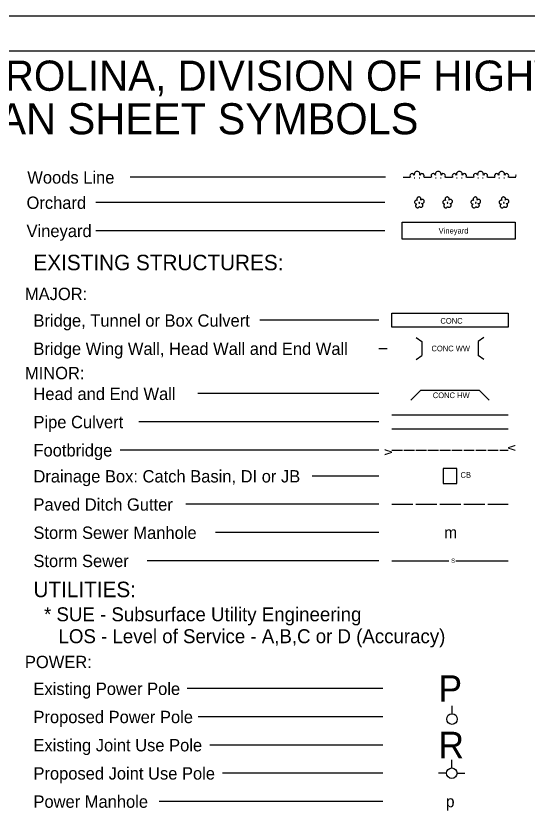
# Model space of a CAD drawing. Extents: x 573077.9 to 573111.9, y -55204.3 to -55182.3.
# Drawn here: x 573096.48 to 573103.74, y -55193.68 to -55182.3 of the extents above; entities that cross this region are included whole.
import ezdxf

# ---------------------------------------------------------------- set-up
doc = ezdxf.new("R2010")
doc.units = 0
doc.layers.add('Sheet Plot Border Inside CELL', color=7, linetype='Continuous')
doc.layers.add('Sheet Symbology CELL', color=7, linetype='Continuous')

msp = doc.modelspace()

# ---------------------------------------------------------------- linework, layer by layer
at = {"layer": 'Sheet Plot Border Inside CELL'}
msp.add_lwpolyline([(573077.854, -55204.298), (573111.854, -55204.298), (573111.854, -55182.298), (573077.854, -55182.298)], close=True, dxfattribs=at)
at = {"layer": 'Sheet Symbology CELL'}
for p, q in [((573101.719, -55184.584), (573098.097, -55184.584)), ((573101.967, -55184.584), (573102.067, -55184.584)), ((573102.126, -55184.594), (573102.136, -55184.594)), ((573102.196, -55184.594), (573102.206, -55184.594)), ((573102.267, -55184.584), (573102.367, -55184.584)), ((573102.426, -55184.594), (573102.436, -55184.594)), ((573102.496, -55184.594), (573102.506, -55184.594)), ((573102.567, -55184.584), (573102.667, -55184.584)), ((573102.726, -55184.594), (573102.736, -55184.594)), ((573102.796, -55184.594), (573102.806, -55184.594)), ((573102.867, -55184.584), (573102.967, -55184.584)), ((573103.026, -55184.594), (573103.036, -55184.594)), ((573103.096, -55184.594), (573103.106, -55184.594)), ((573103.167, -55184.584), (573103.267, -55184.584)), ((573103.326, -55184.594), (573103.336, -55184.594)), ((573103.396, -55184.594), (573103.406, -55184.594)), ((573103.467, -55184.584), (573103.567, -55184.584)), ((573101.708, -55184.942), (573097.609, -55184.942)), ((573101.708, -55185.342), (573097.609, -55185.342)), ((573101.622, -55186.612), (573099.933, -55186.612)), ((573102.151, -55186.855), (573102.233, -55186.912)), ((573103.115, -55186.855), (573103.033, -55186.912)), ((573102.233, -55186.912), (573102.233, -55187.112)), ((573103.033, -55186.912), (573103.033, -55187.112)), ((573101.622, -55187.012), (573101.742, -55187.012)), ((573102.151, -55187.17), (573102.233, -55187.112)), ((573103.115, -55187.17), (573103.033, -55187.112)), ((573101.622, -55187.652), (573099.056, -55187.652)), ((573102.079, -55187.744), (573102.22, -55187.602)), ((573102.22, -55187.602), (573103.045, -55187.602)), ((573103.045, -55187.602), (573103.187, -55187.744)), ((573101.808, -55187.952), (573103.458, -55187.952)), ((573101.622, -55188.052), (573098.218, -55188.052)), ((573101.808, -55188.152), (573103.458, -55188.152)), ((573101.622, -55188.452), (573097.952, -55188.452)), ((573101.808, -55188.452), (573101.958, -55188.452)), ((573101.978, -55188.452), (573102.128, -55188.452)), ((573102.148, -55188.452), (573102.298, -55188.452)), ((573102.318, -55188.452), (573102.468, -55188.452)), ((573102.488, -55188.452), (573102.638, -55188.452)), ((573102.658, -55188.452), (573102.808, -55188.452)), ((573102.828, -55188.452), (573102.978, -55188.452)), ((573102.998, -55188.452), (573103.148, -55188.452)), ((573103.168, -55188.452), (573103.318, -55188.452)), ((573103.338, -55188.452), (573103.458, -55188.452)), ((573101.622, -55188.821), (573100.678, -55188.821)), ((573101.622, -55189.221), (573098.883, -55189.221)), ((573101.808, -55189.221), (573102.108, -55189.221)), ((573102.148, -55189.221), (573102.448, -55189.221)), ((573102.488, -55189.221), (573102.788, -55189.221)), ((573102.828, -55189.221), (573103.128, -55189.221)), ((573103.168, -55189.221), (573103.458, -55189.221)), ((573101.622, -55189.621), (573099.308, -55189.621)), ((573101.622, -55190.021), (573098.338, -55190.021)), ((573101.808, -55190.021), (573102.618, -55190.021)), ((573102.718, -55190.021), (573103.458, -55190.021)), ((573101.678, -55191.835), (573098.904, -55191.835)), ((573102.662, -55192.192), (573102.662, -55192.08)), ((573101.678, -55192.235), (573099.059, -55192.235)), ((573101.678, -55192.635), (573099.227, -55192.635)), ((573102.658, -55192.959), (573102.658, -55192.847)), ((573101.678, -55193.035), (573099.407, -55193.035)), ((573102.583, -55193.034), (573102.47, -55193.034)), ((573102.733, -55193.034), (573102.845, -55193.034)), ((573101.678, -55193.435), (573098.508, -55193.435))]:
    msp.add_line(p, q, dxfattribs=at)
for points in [[(573111.354, -55182.798), (573081.354, -55182.798), (573081.354, -55203.778), (573111.354, -55203.778)], [(573102.537, -55188.927), (573102.729, -55188.927), (573102.729, -55188.715), (573102.537, -55188.715)]]:
    msp.add_lwpolyline(points, close=True, dxfattribs=at)
for points in [[(573102.217, -55184.907), (573102.22, -55184.901), (573102.221, -55184.895), (573102.22, -55184.889), (573102.219, -55184.883), (573102.216, -55184.878), (573102.213, -55184.873), (573102.208, -55184.869), (573102.203, -55184.866), (573102.196, -55184.864), (573102.191, -55184.864), (573102.185, -55184.865), (573102.179, -55184.867), (573102.174, -55184.87), (573102.169, -55184.874), (573102.166, -55184.88), (573102.164, -55184.885), (573102.163, -55184.891), (573102.163, -55184.897), (573102.164, -55184.903), (573102.167, -55184.908), (573102.171, -55184.914), (573102.166, -55184.911), (573102.16, -55184.91), (573102.154, -55184.91), (573102.149, -55184.912), (573102.144, -55184.914), (573102.139, -55184.918), (573102.135, -55184.922), (573102.132, -55184.927), (573102.131, -55184.932), (573102.13, -55184.939), (573102.131, -55184.944), (573102.133, -55184.949), (573102.137, -55184.954), (573102.14, -55184.958), (573102.145, -55184.961), (573102.151, -55184.964), (573102.156, -55184.965), (573102.162, -55184.965), (573102.157, -55184.967), (573102.152, -55184.971), (573102.149, -55184.975), (573102.147, -55184.981), (573102.145, -55184.987), (573102.145, -55184.992), (573102.146, -55184.998), (573102.149, -55185.003), (573102.152, -55185.008), (573102.156, -55185.012), (573102.161, -55185.015), (573102.166, -55185.017), (573102.172, -55185.017), (573102.178, -55185.017), (573102.183, -55185.016), (573102.188, -55185.012), (573102.193, -55185.009), (573102.198, -55185)], [(573102.2, -55184.942), (573102.197, -55184.942), (573102.195, -55184.943), (573102.193, -55184.944), (573102.193, -55184.947), (573102.193, -55184.949), (573102.195, -55184.951), (573102.198, -55184.951), (573102.2, -55184.951), (573102.202, -55184.949), (573102.203, -55184.946), (573102.202, -55184.944), (573102.2, -55184.942)], [(573102.198, -55185), (573102.21, -55185.007), (573102.216, -55185.009), (573102.222, -55185.01), (573102.228, -55185.009), (573102.233, -55185.007), (573102.238, -55185.004), (573102.243, -55185), (573102.246, -55184.995), (573102.248, -55184.99), (573102.25, -55184.984), (573102.249, -55184.978), (573102.248, -55184.972), (573102.244, -55184.966), (573102.241, -55184.962), (573102.236, -55184.959), (573102.23, -55184.956), (573102.236, -55184.957), (573102.243, -55184.957), (573102.248, -55184.955), (573102.254, -55184.952), (573102.259, -55184.949), (573102.263, -55184.944), (573102.266, -55184.938), (573102.267, -55184.932), (573102.268, -55184.926), (573102.267, -55184.92), (573102.265, -55184.914), (573102.261, -55184.909), (573102.256, -55184.904), (573102.251, -55184.901), (573102.245, -55184.899), (573102.239, -55184.898), (573102.233, -55184.898), (573102.227, -55184.9), (573102.222, -55184.903), (573102.217, -55184.907)], [(573102.617, -55184.907), (573102.62, -55184.901), (573102.621, -55184.895), (573102.62, -55184.889), (573102.619, -55184.883), (573102.616, -55184.878), (573102.613, -55184.873), (573102.608, -55184.869), (573102.603, -55184.866), (573102.596, -55184.864), (573102.591, -55184.864), (573102.585, -55184.865), (573102.579, -55184.867), (573102.574, -55184.87), (573102.569, -55184.874), (573102.566, -55184.88), (573102.564, -55184.885), (573102.563, -55184.891), (573102.563, -55184.897), (573102.564, -55184.903), (573102.567, -55184.908), (573102.571, -55184.914), (573102.566, -55184.911), (573102.56, -55184.91), (573102.554, -55184.91), (573102.549, -55184.912), (573102.544, -55184.914), (573102.539, -55184.918), (573102.535, -55184.922), (573102.532, -55184.927), (573102.531, -55184.932), (573102.53, -55184.939), (573102.531, -55184.944), (573102.533, -55184.949), (573102.537, -55184.954), (573102.54, -55184.958), (573102.545, -55184.961), (573102.551, -55184.964), (573102.556, -55184.965), (573102.562, -55184.965), (573102.557, -55184.967), (573102.552, -55184.971), (573102.549, -55184.975), (573102.547, -55184.981), (573102.545, -55184.987), (573102.545, -55184.992), (573102.546, -55184.998), (573102.549, -55185.003), (573102.552, -55185.008), (573102.556, -55185.012), (573102.561, -55185.015), (573102.566, -55185.017), (573102.572, -55185.017), (573102.578, -55185.017), (573102.583, -55185.016), (573102.588, -55185.012), (573102.593, -55185.009), (573102.598, -55185)], [(573102.6, -55184.942), (573102.597, -55184.942), (573102.595, -55184.943), (573102.593, -55184.944), (573102.593, -55184.947), (573102.593, -55184.949), (573102.595, -55184.951), (573102.598, -55184.951), (573102.6, -55184.951), (573102.602, -55184.949), (573102.603, -55184.946), (573102.602, -55184.944), (573102.6, -55184.942)], [(573102.598, -55185), (573102.61, -55185.007), (573102.616, -55185.009), (573102.622, -55185.01), (573102.628, -55185.009), (573102.633, -55185.007), (573102.638, -55185.004), (573102.643, -55185), (573102.646, -55184.995), (573102.648, -55184.99), (573102.65, -55184.984), (573102.649, -55184.978), (573102.648, -55184.972), (573102.644, -55184.966), (573102.641, -55184.962), (573102.636, -55184.959), (573102.63, -55184.956), (573102.636, -55184.957), (573102.643, -55184.957), (573102.648, -55184.955), (573102.654, -55184.952), (573102.659, -55184.949), (573102.663, -55184.944), (573102.666, -55184.938), (573102.667, -55184.932), (573102.668, -55184.926), (573102.667, -55184.92), (573102.665, -55184.914), (573102.661, -55184.909), (573102.656, -55184.904), (573102.651, -55184.901), (573102.645, -55184.899), (573102.639, -55184.898), (573102.633, -55184.898), (573102.627, -55184.9), (573102.622, -55184.903), (573102.617, -55184.907)], [(573103.017, -55184.907), (573103.02, -55184.901), (573103.021, -55184.895), (573103.02, -55184.889), (573103.019, -55184.883), (573103.016, -55184.878), (573103.013, -55184.873), (573103.008, -55184.869), (573103.003, -55184.866), (573102.996, -55184.864), (573102.991, -55184.864), (573102.985, -55184.865), (573102.979, -55184.867), (573102.974, -55184.87), (573102.969, -55184.874), (573102.966, -55184.88), (573102.964, -55184.885), (573102.963, -55184.891), (573102.963, -55184.897), (573102.964, -55184.903), (573102.967, -55184.908), (573102.971, -55184.914), (573102.966, -55184.911), (573102.96, -55184.91), (573102.954, -55184.91), (573102.949, -55184.912), (573102.944, -55184.914), (573102.939, -55184.918), (573102.935, -55184.922), (573102.932, -55184.927), (573102.931, -55184.932), (573102.93, -55184.939), (573102.931, -55184.944), (573102.933, -55184.949), (573102.937, -55184.954), (573102.94, -55184.958), (573102.945, -55184.961), (573102.951, -55184.964), (573102.956, -55184.965), (573102.962, -55184.965), (573102.957, -55184.967), (573102.952, -55184.971), (573102.949, -55184.975), (573102.947, -55184.981), (573102.945, -55184.987), (573102.945, -55184.992), (573102.946, -55184.998), (573102.949, -55185.003), (573102.952, -55185.008), (573102.956, -55185.012), (573102.961, -55185.015), (573102.966, -55185.017), (573102.972, -55185.017), (573102.978, -55185.017), (573102.983, -55185.016), (573102.988, -55185.012), (573102.993, -55185.009), (573102.998, -55185)], [(573103, -55184.942), (573102.997, -55184.942), (573102.995, -55184.943), (573102.993, -55184.944), (573102.993, -55184.947), (573102.993, -55184.949), (573102.995, -55184.951), (573102.998, -55184.951), (573103, -55184.951), (573103.002, -55184.949), (573103.003, -55184.946), (573103.002, -55184.944), (573103, -55184.942)], [(573102.998, -55185), (573103.01, -55185.007), (573103.016, -55185.009), (573103.022, -55185.01), (573103.028, -55185.009), (573103.033, -55185.007), (573103.038, -55185.004), (573103.043, -55185), (573103.046, -55184.995), (573103.048, -55184.99), (573103.05, -55184.984), (573103.049, -55184.978), (573103.048, -55184.972), (573103.044, -55184.966), (573103.041, -55184.962), (573103.036, -55184.959), (573103.03, -55184.956), (573103.036, -55184.957), (573103.043, -55184.957), (573103.048, -55184.955), (573103.054, -55184.952), (573103.059, -55184.949), (573103.063, -55184.944), (573103.066, -55184.938), (573103.067, -55184.932), (573103.068, -55184.926), (573103.067, -55184.92), (573103.065, -55184.914), (573103.061, -55184.909), (573103.056, -55184.904), (573103.051, -55184.901), (573103.045, -55184.899), (573103.039, -55184.898), (573103.033, -55184.898), (573103.027, -55184.9), (573103.022, -55184.903), (573103.017, -55184.907)], [(573103.417, -55184.907), (573103.42, -55184.901), (573103.421, -55184.895), (573103.42, -55184.889), (573103.419, -55184.883), (573103.416, -55184.878), (573103.413, -55184.873), (573103.408, -55184.869), (573103.403, -55184.866), (573103.396, -55184.864), (573103.391, -55184.864), (573103.385, -55184.865), (573103.379, -55184.867), (573103.374, -55184.87), (573103.369, -55184.874), (573103.366, -55184.88), (573103.364, -55184.885), (573103.363, -55184.891), (573103.363, -55184.897), (573103.364, -55184.903), (573103.367, -55184.908), (573103.371, -55184.914), (573103.366, -55184.911), (573103.36, -55184.91), (573103.354, -55184.91), (573103.349, -55184.912), (573103.344, -55184.914), (573103.339, -55184.918), (573103.335, -55184.922), (573103.332, -55184.927), (573103.331, -55184.932), (573103.33, -55184.939), (573103.331, -55184.944), (573103.333, -55184.949), (573103.337, -55184.954), (573103.34, -55184.958), (573103.345, -55184.961), (573103.351, -55184.964), (573103.356, -55184.965), (573103.362, -55184.965), (573103.357, -55184.967), (573103.352, -55184.971), (573103.349, -55184.975), (573103.347, -55184.981), (573103.345, -55184.987), (573103.345, -55184.992), (573103.346, -55184.998), (573103.349, -55185.003), (573103.352, -55185.008), (573103.356, -55185.012), (573103.361, -55185.015), (573103.366, -55185.017), (573103.372, -55185.017), (573103.378, -55185.017), (573103.383, -55185.016), (573103.388, -55185.012), (573103.393, -55185.009), (573103.398, -55185)], [(573103.4, -55184.942), (573103.397, -55184.942), (573103.395, -55184.943), (573103.393, -55184.944), (573103.393, -55184.947), (573103.393, -55184.949), (573103.395, -55184.951), (573103.398, -55184.951), (573103.4, -55184.951), (573103.402, -55184.949), (573103.403, -55184.946), (573103.402, -55184.944), (573103.4, -55184.942)], [(573103.398, -55185), (573103.41, -55185.007), (573103.416, -55185.009), (573103.422, -55185.01), (573103.428, -55185.009), (573103.433, -55185.007), (573103.438, -55185.004), (573103.443, -55185), (573103.446, -55184.995), (573103.448, -55184.99), (573103.45, -55184.984), (573103.449, -55184.978), (573103.448, -55184.972), (573103.444, -55184.966), (573103.441, -55184.962), (573103.436, -55184.959), (573103.43, -55184.956), (573103.436, -55184.957), (573103.443, -55184.957), (573103.448, -55184.955), (573103.454, -55184.952), (573103.459, -55184.949), (573103.463, -55184.944), (573103.466, -55184.938), (573103.467, -55184.932), (573103.468, -55184.926), (573103.467, -55184.92), (573103.465, -55184.914), (573103.461, -55184.909), (573103.456, -55184.904), (573103.451, -55184.901), (573103.445, -55184.899), (573103.439, -55184.898), (573103.433, -55184.898), (573103.427, -55184.9), (573103.422, -55184.903), (573103.417, -55184.907)], [(573101.956, -55185.222), (573103.556, -55185.222), (573103.556, -55185.462), (573101.956, -55185.462), (573101.956, -55185.222)], [(573101.808, -55186.512), (573103.458, -55186.512), (573103.458, -55186.712), (573101.808, -55186.712), (573101.808, -55186.512)]]:
    msp.add_lwpolyline(points, dxfattribs=at)
for centre in [(573102.662, -55192.267), (573102.658, -55193.035)]:
    msp.add_circle(centre, 0.075, dxfattribs=at)
for centre, radius, start, end in [((573102.096, -55184.563), 0.0316, 18.435, 219.2315), ((573102.166, -55184.543), 0.0412, 345.9638, 194.0362), ((573102.236, -55184.563), 0.0316, 320.7685, 161.5651), ((573102.396, -55184.563), 0.0316, 18.435, 219.2315), ((573102.466, -55184.543), 0.0412, 345.9638, 194.0362), ((573102.536, -55184.563), 0.0316, 320.7685, 161.5651), ((573102.696, -55184.563), 0.0316, 18.435, 219.2315), ((573102.766, -55184.543), 0.0412, 345.9638, 194.0362), ((573102.836, -55184.563), 0.0316, 320.7685, 161.5651), ((573102.996, -55184.563), 0.0316, 18.435, 219.2315), ((573103.066, -55184.543), 0.0412, 345.9638, 194.0362), ((573103.136, -55184.563), 0.0316, 320.7685, 161.5651), ((573103.296, -55184.563), 0.0316, 18.435, 219.2315), ((573103.366, -55184.543), 0.0412, 345.9638, 194.0362), ((573103.436, -55184.563), 0.0316, 320.7685, 161.5651), ((573103.596, -55184.563), 0.0316, 156.251, 203.749)]:
    msp.add_arc(centre, radius, start, end, dxfattribs=at)

# ---------------------------------------------------------------- texts
for s, height, p in [('STATE OF NORTH CAROLINA, DIVISION OF HIGHWAYS', 0.42838, (573090.365, -55183.358)), ('CONVENTIONAL  PLAN SHEET SYMBOLS', 0.44065, (573090.528, -55183.975)), ('Woods Line', 0.175, (573096.636, -55184.674)), ('Orchard', 0.175, (573096.625, -55185.033)), ('Vineyard', 0.175, (573096.625, -55185.433)), ('EXISTING STRUCTURES:', 0.22, (573096.723, -55185.903)), ('MAJOR:', 0.175, (573096.602, -55186.326)), ('Bridge, Tunnel or Box Culvert', 0.175, (573096.723, -55186.703)), ('CONC', 0.08, (573102.497, -55186.66)), ('Bridge Wing Wall, Head Wall and End Wall', 0.175, (573096.723, -55187.103)), ('MINOR:', 0.175, (573096.602, -55187.448)), ('Head and End Wall', 0.175, (573096.723, -55187.743)), ('Pipe Culvert', 0.175, (573096.723, -55188.143)), ('Footbridge', 0.175, (573096.723, -55188.543)), ('Drainage Box: Catch Basin, DI or JB', 0.175, (573096.723, -55188.912)), ('Paved Ditch Gutter', 0.175, (573096.723, -55189.312)), ('Storm Sewer Manhole', 0.175, (573096.723, -55189.712)), ('m', 0.165, (573102.55, -55189.704)), ('Storm Sewer', 0.175, (573096.723, -55190.112)), ('S', 0.06, (573102.65, -55190.051)), ('UTILITIES:', 0.22, (573096.723, -55190.539)), ('POWER:', 0.175, (573096.602, -55191.545)), ('P', 0.375, (573102.47, -55192.022)), ('Existing Power Pole', 0.175, (573096.723, -55191.925)), ('Proposed Power Pole', 0.175, (573096.723, -55192.325)), ('R', 0.375, (573102.47, -55192.822)), ('Existing Joint Use Pole', 0.175, (573096.723, -55192.725)), ('Proposed Joint Use Pole', 0.175, (573096.723, -55193.125)), ('Power Manhole', 0.175, (573096.723, -55193.525)), ('p', 0.165, (573102.575, -55193.517))]:
    msp.add_text(s, height=height, dxfattribs=at).set_placement(p)
for s, height, rotation, p in [('Vineyard', 0.08, 0, (573102.472, -55185.382)), ('CONC WW', 0.08, 0, (573102.37, -55187.052)), ('CONC HW', 0.08, 360, (573102.389, -55187.716)), ('v', 0.132, 89.7591, (573101.808, -55188.527)), ('v', 0.132, 270.2409, (573103.458, -55188.378)), ('CB', 0.08, 360, (573102.782, -55188.845)), ('* SUE - Subsurface Utility Engineering', 0.198, 360, (573096.873, -55190.88)), ('LOS - Level of Service - A,B,C or D (Accuracy) ', 0.198, 360, (573097.079, -55191.191))]:
    msp.add_text(s, height=height, rotation=rotation, dxfattribs=at).set_placement(p)

doc.saveas('drawing.dxf')
